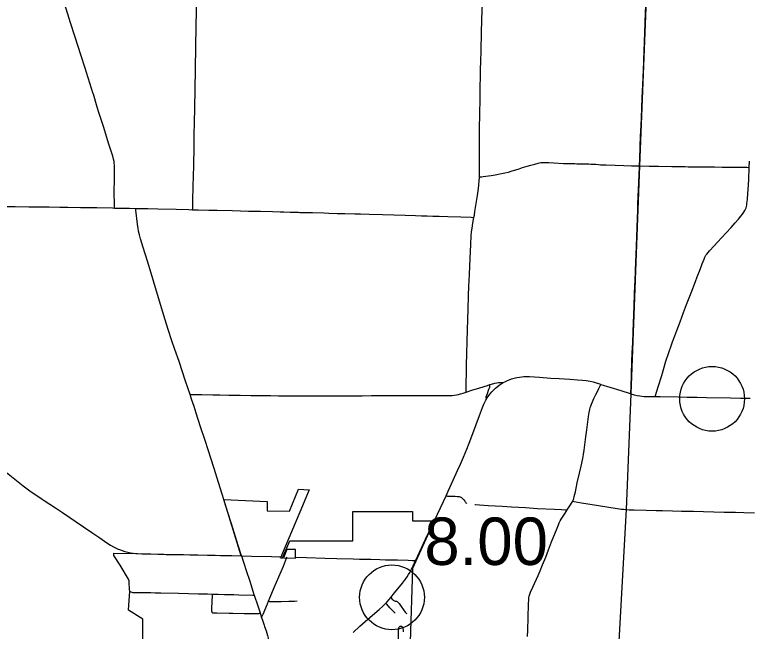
# Model space of a CAD drawing. Extents: x 9078 to 9739, y 4248 to 4966.
# Drawn here: x 9264.8 to 9349.9, y 4556.7 to 4628.2 of the extents above; entities that cross this region are included whole.
import ezdxf

# ---------------------------------------------------------------- set-up
doc = ezdxf.new("R2010")
doc.units = 0
for name, color, linetype in [('Default', 7, 'Continuous'), ('GM_X_City_Street', 7, 'Continuous'), ('GM_X_Corporation', 7, 'Continuous'), ('GM_X_County_Road', 7, 'Continuous'), ('GM_X_State_Route', 7, 'Continuous'), ('GM_X_Township', 7, 'Continuous'), ('GM_X_Township_Road', 7, 'Continuous'), ('GM_X_US_Route', 7, 'Continuous')]:
    doc.layers.add(name, color=color, linetype=linetype)

msp = doc.modelspace()

# ---------------------------------------------------------------- linework, layer by layer
at = {"layer": 'Default'}
for centre in [(9345.582, 4583.648), (9308.502, 4560.636)]:
    msp.add_circle(centre, 3.75, dxfattribs=at)
at = {"layer": 'GM_X_City_Street'}
for points in [[(9291.063, 4565.445), (9292.248, 4565.426), (9294.555, 4565.36), (9295.461, 4565.331), (9295.654, 4565.326)], [(9294.207, 4560.179), (9294.395, 4560.636), (9294.872, 4561.766), (9295.921, 4564.252), (9296.171, 4564.857), (9296.299, 4565.158), (9296.365, 4565.311)], [(9295.886, 4565.316), (9295.98, 4565.316)], [(9297.363, 4565.292), (9298.595, 4565.261), (9300.721, 4565.195), (9302.112, 4565.155), (9303.993, 4565.094), (9304.728, 4565.072), (9306.037, 4565.042), (9307.1, 4565.014), (9307.754, 4564.999), (9308.515, 4564.985), (9309.154, 4564.965), (9310.393, 4564.933), (9310.884, 4564.916), (9311.135, 4564.914), (9311.243, 4564.913)], [(9278.224, 4561.315), (9278.275, 4561.27), (9278.356, 4561.22), (9278.435, 4561.2), (9278.601, 4561.186), (9278.754, 4561.186), (9279.257, 4561.192), (9279.915, 4561.194), (9280.573, 4561.189), (9281.066, 4561.172), (9281.723, 4561.154), (9283.778, 4561.102), (9286.08, 4561.049), (9287.149, 4561.029), (9287.715, 4561.014)], [(9287.692, 4558.876), (9287.672, 4558.912), (9287.659, 4558.947), (9287.649, 4558.989), (9287.646, 4559.025), (9287.653, 4559.423), (9287.678, 4560.084), (9287.71, 4560.898), (9287.715, 4561.014)], [(9287.715, 4561.014), (9288.382, 4560.996), (9289.119, 4560.977), (9289.446, 4560.965), (9289.773, 4560.961), (9290.184, 4560.951), (9290.759, 4560.938), (9292.398, 4560.874), (9292.549, 4560.869)], [(9308.356, 4560.612), (9308.397, 4560.57), (9308.494, 4560.471), (9308.597, 4560.367), (9308.657, 4560.311), (9308.722, 4560.264), (9308.794, 4560.227), (9308.873, 4560.21), (9308.953, 4560.201), (9309.031, 4560.181), (9309.103, 4560.144), (9309.164, 4560.093), (9309.318, 4559.904), (9309.56, 4559.58), (9309.842, 4559.185), (9310.044, 4558.932), (9310.152, 4558.812), (9310.212, 4558.758)], [(9293.404, 4558.315), (9293.469, 4558.453), (9293.574, 4558.675), (9294.079, 4559.882), (9294.207, 4560.179)], [(9294.207, 4560.179), (9294.327, 4560.149), (9294.521, 4560.145), (9294.685, 4560.156), (9294.862, 4560.164), (9295.173, 4560.169), (9295.662, 4560.165), (9296.559, 4560.18), (9297.214, 4560.194), (9297.541, 4560.212)], [(9308.884, 4558.793), (9308.71, 4558.961), (9308.484, 4559.19), (9308.27, 4559.43), (9307.898, 4559.853), (9307.799, 4559.965)], [(9287.692, 4558.876), (9287.715, 4558.857), (9287.751, 4558.841), (9287.823, 4558.834), (9287.904, 4558.831), (9288.232, 4558.829), (9289.662, 4558.801), (9290.055, 4558.791), (9291.366, 4558.775), (9292.185, 4558.751), (9292.759, 4558.746), (9293.05, 4558.753), (9293.113, 4558.771), (9293.159, 4558.796), (9293.224, 4558.831)], [(9309.828, 4556.623), (9309.821, 4556.87), (9309.813, 4556.951), (9309.799, 4557.031), (9309.778, 4557.088), (9309.753, 4557.133), (9309.724, 4557.173), (9309.696, 4557.202), (9309.66, 4557.229), (9309.627, 4557.248), (9309.585, 4557.265), (9309.545, 4557.271), (9309.516, 4557.273), (9309.475, 4557.268), (9309.442, 4557.258), (9309.403, 4557.238), (9309.376, 4557.22), (9309.345, 4557.196), (9309.318, 4557.17), (9309.284, 4557.12), (9309.256, 4557.055), (9309.237, 4556.976), (9309.227, 4556.894), (9309.22, 4556.731), (9309.235, 4555.67)]]:
    msp.add_lwpolyline(points, dxfattribs=at)
at = {"layer": 'GM_X_Corporation'}
msp.add_lwpolyline([(9279.666, 4554.438), (9279.663, 4558.107), (9277.986, 4559.165), (9278.156, 4561.349), (9278.095, 4561.54), (9278.076, 4562.376), (9278.054, 4562.558), (9277.986, 4562.751), (9277.025, 4564.348), (9276.283, 4565.504), (9276.271, 4565.775), (9278.822, 4565.731), (9280.387, 4565.668), (9282.335, 4565.618), (9288.018, 4565.52), (9289.479, 4565.493), (9291.052, 4565.44), (9289.011, 4571.979), (9294.041, 4571.745), (9294.059, 4570.659), (9296.616, 4570.631), (9297.682, 4573.156), (9298.927, 4573.115), (9297.822, 4570.498), (9295.6, 4565.233), (9295.835, 4565.226), (9296.665, 4567.191), (9303.974, 4567.192), (9303.974, 4570.592), (9310.879, 4570.593), (9310.88, 4569.517), (9313.38, 4569.486), (9310.88, 4563.986), (9310.619, 4555.475)], dxfattribs=at)
msp.add_lwpolyline([(9295.942, 4565.222), (9297.326, 4565.19), (9297.317, 4566.19), (9296.343, 4566.181)], close=True, dxfattribs=at)
at = {"layer": 'GM_X_County_Road'}
for points in [[(9337.163, 4610.641), (9337.194, 4611.457), (9337.248, 4612.852), (9337.266, 4613.282), (9337.286, 4613.743), (9337.301, 4614.099), (9337.33, 4614.694), (9337.361, 4615.362), (9337.402, 4616.213), (9337.494, 4618.509), (9337.564, 4620.067), (9337.625, 4621.789), (9337.671, 4622.773), (9337.725, 4624.167), (9337.749, 4624.821), (9337.761, 4625.151), (9337.79, 4625.971), (9337.842, 4627.366), (9337.88, 4628.35), (9337.953, 4630.154), (9337.976, 4630.791)], [(9336.158, 4584.244), (9336.162, 4584.337), (9336.189, 4585.051), (9336.296, 4587.922), (9336.339, 4588.988), (9336.387, 4590.136), (9336.439, 4591.448), (9336.472, 4592.432), (9336.546, 4594.4), (9336.604, 4595.876), (9336.656, 4597.435), (9336.699, 4598.35), (9336.708, 4598.55), (9336.752, 4599.484), (9336.795, 4600.386), (9336.842, 4601.37), (9336.872, 4602.436), (9336.903, 4603.503), (9336.939, 4604.569), (9336.967, 4605.554), (9336.991, 4606.209), (9337.03, 4607.111), (9337.091, 4608.669), (9337.125, 4609.653), (9337.156, 4610.473), (9337.163, 4610.641)], [(9259.346, 4605.998), (9259.626, 4605.989), (9260.446, 4605.977), (9261.594, 4605.963), (9263.481, 4605.945), (9264.876, 4605.934), (9266.435, 4605.911), (9267.748, 4605.902), (9268.815, 4605.892), (9270.046, 4605.88), (9270.948, 4605.865), (9272.426, 4605.842), (9274.313, 4605.809), (9276.118, 4605.771), (9276.363, 4605.767)], [(9276.363, 4605.767), (9277.266, 4605.749), (9278.087, 4605.739), (9278.819, 4605.729)], [(9285.116, 4584.16), (9284.596, 4585.71), (9283.843, 4587.964), (9283.368, 4589.361), (9283.022, 4590.369), (9282.586, 4591.692), (9282.24, 4592.787), (9281.696, 4594.591), (9280.92, 4597.183), (9280.603, 4598.2), (9280.174, 4599.611), (9279.691, 4601.177), (9279.383, 4602.197), (9279.25, 4602.672), (9279.157, 4603.072), (9279.098, 4603.395), (9279.029, 4603.883), (9278.835, 4605.512), (9278.83, 4605.595), (9278.819, 4605.729)], [(9278.819, 4605.729), (9278.989, 4605.726), (9280.22, 4605.703), (9281.369, 4605.681), (9283.501, 4605.619), (9284.978, 4605.58), (9285.417, 4605.569)], [(9285.417, 4605.569), (9286.044, 4605.553), (9287.275, 4605.526), (9288.259, 4605.501), (9289.982, 4605.467), (9290.966, 4605.444), (9291.869, 4605.42), (9293.263, 4605.387), (9294.657, 4605.345), (9295.559, 4605.323), (9295.968, 4605.315), (9296.706, 4605.29), (9297.434, 4605.271), (9297.671, 4605.267), (9297.819, 4605.259), (9298.119, 4605.247), (9298.487, 4605.243), (9298.892, 4605.243), (9299.308, 4605.231), (9300.597, 4605.191), (9301.185, 4605.172), (9302.165, 4605.148), (9303.062, 4605.124), (9304.219, 4605.104), (9304.875, 4605.084), (9305.86, 4605.06), (9307.409, 4605.012), (9308.702, 4604.981), (9310.026, 4604.945), (9311.243, 4604.901), (9311.919, 4604.877), (9312.439, 4604.858)], [(9312.439, 4604.858), (9312.568, 4604.853), (9313.224, 4604.833), (9313.973, 4604.805), (9314.957, 4604.778), (9316.494, 4604.734), (9317.659, 4604.696), (9317.979, 4604.671)], [(9317.094, 4584.415), (9317.089, 4584.855), (9317.102, 4585.511), (9317.13, 4586.612), (9317.152, 4587.557), (9317.242, 4591.65), (9317.314, 4594.024), (9317.371, 4595.578), (9317.415, 4596.726), (9317.44, 4597.308), (9317.478, 4598.114), (9317.557, 4599.914), (9317.625, 4601.55), (9317.682, 4602.531), (9317.724, 4603.022), (9317.775, 4603.429), (9317.865, 4603.996), (9317.979, 4604.671)], [(9317.094, 4584.415), (9317.762, 4584.634), (9318.693, 4584.94), (9319.551, 4585.209), (9319.835, 4585.291)], [(9319.484, 4583.679), (9319.446, 4583.722), (9319.429, 4583.751), (9319.417, 4583.786), (9319.417, 4583.791), (9319.412, 4583.816), (9319.413, 4583.839), (9319.421, 4583.89), (9319.556, 4584.277), (9319.734, 4584.75), (9319.822, 4584.985), (9319.841, 4585.067), (9319.845, 4585.112), (9319.848, 4585.144), (9319.847, 4585.186), (9319.843, 4585.237), (9319.835, 4585.291)], [(9319.835, 4585.291), (9320.023, 4585.346), (9320.419, 4585.449), (9320.66, 4585.499), (9320.823, 4585.522), (9320.973, 4585.538), (9321.195, 4585.538), (9321.396, 4585.53)], [(9289.023, 4571.988), (9288.827, 4572.608), (9288.414, 4573.939), (9287.897, 4575.581), (9287.526, 4576.752), (9287.251, 4577.611), (9286.822, 4578.937), (9286.337, 4580.416), (9285.832, 4581.975), (9285.574, 4582.753), (9285.299, 4583.615), (9285.116, 4584.16)], [(9291.063, 4565.445), (9290.68, 4566.658), (9290.225, 4568.142), (9289.911, 4569.157), (9289.497, 4570.482), (9289.225, 4571.339), (9289.023, 4571.988)], [(9314.776, 4572.417), (9314.85, 4572.403), (9314.949, 4572.382), (9315.06, 4572.375), (9315.225, 4572.371), (9315.488, 4572.366), (9315.819, 4572.356), (9316.066, 4572.339), (9316.181, 4572.328), (9316.274, 4572.309), (9316.389, 4572.271), (9316.467, 4572.242), (9316.541, 4572.207), (9316.61, 4572.162), (9316.673, 4572.109), (9316.73, 4572.05), (9316.832, 4571.922), (9316.926, 4571.787), (9316.973, 4571.719), (9317.021, 4571.652), (9317.072, 4571.59), (9317.127, 4571.538), (9317.186, 4571.496)], [(9328.778, 4570.764), (9329.025, 4571.116), (9329.462, 4571.797)], [(9329.462, 4571.797), (9329.615, 4571.742), (9330.456, 4571.595), (9331.672, 4571.404), (9334.346, 4570.981), (9335.076, 4570.872), (9335.335, 4570.843)], [(9318.083, 4571.385), (9318.165, 4571.379), (9318.655, 4571.349), (9319.636, 4571.287), (9321.271, 4571.195), (9322.333, 4571.134), (9323.968, 4571.039), (9325.357, 4570.952), (9327.32, 4570.84), (9328.137, 4570.799), (9328.613, 4570.778), (9328.778, 4570.764)], [(9335.335, 4570.843), (9335.565, 4570.817), (9335.974, 4570.786), (9336.548, 4570.767), (9337.942, 4570.742), (9339.091, 4570.718), (9339.829, 4570.7), (9340.977, 4570.679), (9342.043, 4570.643), (9343.437, 4570.613), (9344.585, 4570.579), (9346.963, 4570.522), (9348.275, 4570.497), (9349.26, 4570.469), (9350.49, 4570.441)]]:
    msp.add_lwpolyline(points, dxfattribs=at)
at = {"layer": 'GM_X_State_Route'}
for points in [[(9262.951, 4575.757), (9263.466, 4575.386), (9264.058, 4574.945), (9264.637, 4574.489), (9265.209, 4574.022), (9265.784, 4573.557), (9266.239, 4573.207), (9266.705, 4572.87), (9267.248, 4572.5), (9268.005, 4572.009), (9268.216, 4571.871)], [(9268.216, 4571.871), (9269.515, 4571.019), (9270.333, 4570.471), (9272.776, 4568.81), (9273.862, 4568.073), (9274.675, 4567.517), (9274.936, 4567.34)], [(9274.936, 4567.34), (9275.491, 4566.965), (9275.906, 4566.699), (9276.262, 4566.493), (9276.482, 4566.379), (9276.801, 4566.238), (9276.951, 4566.174), (9277.259, 4566.058), (9277.573, 4565.957), (9277.892, 4565.876), (9278.216, 4565.813), (9278.542, 4565.766), (9278.904, 4565.732)], [(9278.904, 4565.732), (9279.033, 4565.72), (9279.526, 4565.693), (9280.592, 4565.668), (9282.069, 4565.639), (9283.202, 4565.613)], [(9283.202, 4565.613), (9283.382, 4565.609), (9284.367, 4565.589), (9285.104, 4565.571), (9286.007, 4565.555), (9287.155, 4565.531), (9288.632, 4565.501), (9289.945, 4565.481), (9291.063, 4565.445)], [(9291.063, 4565.445), (9291.292, 4564.726), (9291.65, 4563.633), (9291.984, 4562.617), (9292.184, 4561.992), (9292.514, 4560.976), (9292.549, 4560.869), (9292.952, 4559.65), (9293.224, 4558.831), (9293.237, 4558.791), (9293.32, 4558.559), (9293.333, 4558.522)], [(9293.333, 4558.522), (9293.404, 4558.315), (9293.559, 4557.861), (9293.711, 4557.392), (9293.754, 4557.262)], [(9293.754, 4557.262), (9293.918, 4556.767), (9294.095, 4556.221), (9294.136, 4556.064), (9294.162, 4555.905), (9294.174, 4555.743), (9294.191, 4555.105)]]:
    msp.add_lwpolyline(points, dxfattribs=at)
at = {"layer": 'GM_X_Township'}
msp.add_lwpolyline([(9312.647, 4658.232), (9312.261, 4631.593), (9319.031, 4631.42), (9322.506, 4631.285), (9323.21, 4631.298), (9334.307, 4630.93), (9337.049, 4630.853), (9337.941, 4630.782), (9337.951, 4630.023), (9337.165, 4610.668), (9336.171, 4584.222), (9335.616, 4570.813), (9334.675, 4553.48)], dxfattribs=at)
at = {"layer": 'GM_X_Township_Road'}
for points in [[(9273.897, 4619.017), (9272.915, 4622.087), (9272.492, 4623.416), (9271.76, 4625.68), (9271.263, 4627.243), (9270.597, 4629.356), (9270.179, 4630.686), (9269.734, 4632.094), (9269.594, 4632.521)], [(9285.417, 4605.569), (9285.426, 4605.761), (9285.43, 4605.843), (9285.452, 4606.664), (9285.489, 4608.223), (9285.52, 4609.536), (9285.539, 4610.602), (9285.554, 4611.341), (9285.575, 4612.161), (9285.591, 4612.981), (9285.61, 4614.212), (9285.636, 4615.771), (9285.665, 4617.248), (9285.71, 4619.628), (9285.748, 4621.761), (9285.764, 4622.746), (9285.774, 4623.567), (9285.788, 4624.551), (9285.822, 4626.684), (9285.85, 4628.736), (9285.867, 4630.049), (9285.884, 4631.526), (9285.882, 4632.201)], [(9318.725, 4620.057), (9318.74, 4620.724), (9318.768, 4621.953), (9318.792, 4622.69), (9318.834, 4624.082), (9318.879, 4626.048), (9318.926, 4627.604), (9318.953, 4628.587), (9319.008, 4630.389), (9319.035, 4631.045), (9319.051, 4631.387)], [(9318.637, 4609.347), (9318.646, 4609.665), (9318.652, 4610.402), (9318.642, 4611.139), (9318.639, 4612.204), (9318.641, 4613.024), (9318.645, 4613.515), (9318.657, 4614.908), (9318.681, 4616.71), (9318.704, 4618.349), (9318.721, 4619.413), (9318.72, 4619.823), (9318.723, 4619.952), (9318.725, 4620.057)], [(9276.363, 4605.767), (9276.358, 4605.954), (9276.35, 4606.282), (9276.345, 4607.43), (9276.36, 4609.317), (9276.363, 4610.384), (9276.361, 4610.719), (9276.341, 4610.947), (9276.313, 4611.172), (9276.252, 4611.442), (9276.171, 4611.76), (9275.729, 4613.169), (9275.08, 4615.2), (9274.568, 4616.845), (9274.374, 4617.472), (9273.915, 4618.962), (9273.897, 4619.017)], [(9318.637, 4609.347), (9318.763, 4609.363), (9318.842, 4609.372), (9318.921, 4609.382), (9319.083, 4609.402), (9319.978, 4609.527), (9320.463, 4609.607), (9321.187, 4609.754), (9321.587, 4609.841), (9321.986, 4609.935), (9322.301, 4610.028), (9323.239, 4610.327), (9323.631, 4610.447), (9324.181, 4610.607), (9324.573, 4610.721), (9325.044, 4610.86), (9325.438, 4610.971), (9325.598, 4611.007), (9325.76, 4611.033), (9325.923, 4611.047), (9326.169, 4611.053), (9326.661, 4611.042), (9327.234, 4611.012), (9328.384, 4610.946), (9329.158, 4610.918), (9329.517, 4610.914), (9329.693, 4610.91), (9329.912, 4610.906), (9330.177, 4610.903), (9330.439, 4610.902), (9330.826, 4610.894), (9331.114, 4610.878), (9331.313, 4610.87), (9331.545, 4610.854), (9331.76, 4610.851), (9331.96, 4610.842), (9332.127, 4610.831), (9332.427, 4610.811), (9332.666, 4610.791), (9332.889, 4610.777), (9333.297, 4610.766), (9334.365, 4610.739), (9335.349, 4610.704), (9336.25, 4610.669), (9336.906, 4610.648), (9337.163, 4610.641)], [(9349.89, 4610.478), (9349.922, 4611.188)], [(9337.163, 4610.641), (9338.301, 4610.611), (9339.367, 4610.602), (9340.926, 4610.589), (9341.829, 4610.572), (9342.452, 4610.561), (9342.792, 4610.557), (9343.305, 4610.556), (9343.715, 4610.558), (9344.289, 4610.551), (9345.192, 4610.538), (9345.848, 4610.534), (9346.751, 4610.519), (9348.392, 4610.504), (9349.623, 4610.483), (9349.89, 4610.478)], [(9338.99, 4583.907), (9339.024, 4584.02), (9339.329, 4585.036), (9339.741, 4586.369), (9340.24, 4588.017), (9340.569, 4589.031), (9340.837, 4589.806), (9341.002, 4590.269), (9341.263, 4590.959), (9341.497, 4591.572), (9341.872, 4592.57), (9342.283, 4593.643), (9342.63, 4594.564), (9343.156, 4595.944), (9343.659, 4597.244), (9343.869, 4597.778), (9344.187, 4598.623), (9344.448, 4599.314), (9344.656, 4599.848), (9344.757, 4600.07), (9344.874, 4600.284), (9344.963, 4600.419), (9345.112, 4600.613), (9345.274, 4600.797), (9345.836, 4601.394), (9346.22, 4601.821), (9347.22, 4602.907), (9347.771, 4603.515), (9348.269, 4604.06), (9348.651, 4604.49), (9348.912, 4604.807), (9349.11, 4605.071), (9349.248, 4605.277), (9349.372, 4605.491), (9349.445, 4605.64), (9349.508, 4605.793), (9349.557, 4605.951), (9349.594, 4606.113), (9349.621, 4606.276), (9349.671, 4606.767), (9349.739, 4607.502), (9349.762, 4607.83), (9349.795, 4608.485), (9349.819, 4609.058), (9349.889, 4610.451), (9349.89, 4610.478)], [(9317.979, 4604.671), (9318.046, 4604.951), (9318.11, 4605.365), (9318.409, 4607.225), (9318.526, 4608.035), (9318.572, 4608.442), (9318.614, 4608.93), (9318.633, 4609.257), (9318.637, 4609.347)], [(9329.462, 4571.797), (9329.562, 4572.076), (9329.618, 4572.315), (9329.741, 4572.875), (9329.97, 4573.916), (9330.224, 4575.035), (9330.402, 4575.834), (9330.596, 4576.714), (9330.691, 4577.196), (9330.764, 4577.682), (9330.844, 4578.333), (9330.953, 4579.228), (9331.054, 4580.041), (9331.268, 4581.583), (9331.344, 4582.069), (9331.408, 4582.391), (9331.471, 4582.628), (9331.521, 4582.784), (9331.606, 4583.013), (9331.733, 4583.315), (9331.902, 4583.688), (9332.114, 4584.132), (9332.332, 4584.573), (9332.471, 4584.847), (9332.628, 4585.156), (9332.712, 4585.321)], [(9285.116, 4584.16), (9285.219, 4584.159), (9286.488, 4584.147), (9287.749, 4584.122), (9288.567, 4584.105), (9289.608, 4584.084), (9290.922, 4584.061), (9292.153, 4584.038), (9293.713, 4584.022), (9294.453, 4584.014), (9295.361, 4584.007), (9297.157, 4584.004), (9298.641, 4584.001), (9300.859, 4583.997), (9302.255, 4584.001), (9302.83, 4584.004), (9303.651, 4584.007), (9303.979, 4584.008), (9305.046, 4584.013), (9306.114, 4584.017), (9307.182, 4584.017), (9307.838, 4584.02), (9309.234, 4584.033), (9311.05, 4584.037), (9313.505, 4584.043), (9315.066, 4584.037), (9315.476, 4584.045), (9315.72, 4584.061), (9315.965, 4584.091), (9316.207, 4584.147), (9316.432, 4584.208), (9316.747, 4584.301), (9317.094, 4584.415)], [(9324.214, 4556.086), (9324.242, 4556.825), (9324.291, 4558.303), (9324.333, 4559.863), (9324.351, 4560.375), (9324.362, 4560.6), (9324.383, 4560.763), (9324.416, 4560.883), (9324.463, 4561.014), (9324.555, 4561.231), (9324.825, 4561.831), (9325.438, 4563.176), (9325.669, 4563.703), (9325.945, 4564.389), (9326.306, 4565.306), (9326.628, 4566.151), (9326.991, 4567.067), (9327.626, 4568.671), (9327.776, 4569.053), (9327.87, 4569.281), (9327.978, 4569.502), (9328.102, 4569.714), (9328.326, 4570.058), (9328.553, 4570.401), (9328.778, 4570.764)]]:
    msp.add_lwpolyline(points, dxfattribs=at)
at = {"layer": 'GM_X_US_Route'}
for points in [[(9313.772, 4570.285), (9314.464, 4571.744), (9314.776, 4572.417), (9315.016, 4572.935), (9315.594, 4574.204), (9316.095, 4575.327), (9316.43, 4576.076), (9316.798, 4576.9), (9317.181, 4577.806), (9317.451, 4578.493), (9317.876, 4579.647), (9318.639, 4581.727), (9318.982, 4582.65), (9319.137, 4583.032), (9319.242, 4583.255), (9319.359, 4583.473), (9319.484, 4583.679), (9319.53, 4583.755), (9319.715, 4584.028), (9319.864, 4584.225), (9320.078, 4584.476), (9320.248, 4584.656), (9320.488, 4584.882), (9320.676, 4585.042), (9320.938, 4585.242), (9321.141, 4585.383), (9321.396, 4585.53), (9321.569, 4585.63), (9321.868, 4585.771), (9322.096, 4585.865), (9322.329, 4585.947), (9322.646, 4586.04), (9322.966, 4586.116), (9323.291, 4586.174), (9323.536, 4586.206), (9323.783, 4586.224), (9324.03, 4586.229), (9324.441, 4586.217), (9325.588, 4586.149), (9326.898, 4586.061), (9327.88, 4585.993), (9329.108, 4585.919), (9330.009, 4585.862), (9330.582, 4585.822), (9330.991, 4585.782), (9331.235, 4585.744), (9331.477, 4585.691), (9331.795, 4585.606), (9332.657, 4585.338), (9332.712, 4585.321), (9333.753, 4584.996), (9335.006, 4584.602), (9336.102, 4584.26), (9336.158, 4584.244), (9336.574, 4584.123), (9336.891, 4584.046), (9337.213, 4583.987), (9337.456, 4583.955), (9337.7, 4583.933), (9338.19, 4583.918), (9338.99, 4583.907), (9339.585, 4583.898), (9341.636, 4583.867), (9342.702, 4583.844), (9343.85, 4583.822), (9344.917, 4583.804), (9347.706, 4583.754), (9348.854, 4583.728), (9350.003, 4583.713)], [(9313.397, 4569.495), (9313.418, 4569.539), (9313.772, 4570.285)], [(9310.828, 4564.02), (9311.243, 4564.913), (9311.497, 4565.46), (9312.401, 4567.386), (9313.167, 4569.014), (9313.397, 4569.495)], [(9304.001, 4556.564), (9304.791, 4557.279), (9305.712, 4558.096), (9307.01, 4559.226), (9307.436, 4559.61), (9307.731, 4559.894), (9307.799, 4559.965), (9307.9, 4560.071), (9308.168, 4560.379), (9308.356, 4560.612), (9308.785, 4561.145), (9309.713, 4562.293), (9310.065, 4562.745), (9310.256, 4563.011), (9310.434, 4563.285), (9310.598, 4563.568), (9310.77, 4563.902), (9310.828, 4564.02)]]:
    msp.add_lwpolyline(points, dxfattribs=at)

# ---------------------------------------------------------------- texts
at = {"layer": 'Default'}
msp.add_text('8.00', height=5.5, dxfattribs=at).set_placement((9312.252, 4564.386))

doc.saveas('drawing.dxf')
